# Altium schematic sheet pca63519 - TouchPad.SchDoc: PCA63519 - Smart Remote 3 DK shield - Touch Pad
size A4; DocumentNumber: 6; Revision: 1.2.1; SheetNumber: 6; SheetTotal: 6; DrawnBy: GETR; ProjectNumber: 4414; DocumentSize: A4; PCBRevision: 0049GETR; PCAName: PCA63519; PCBNumber: 400129
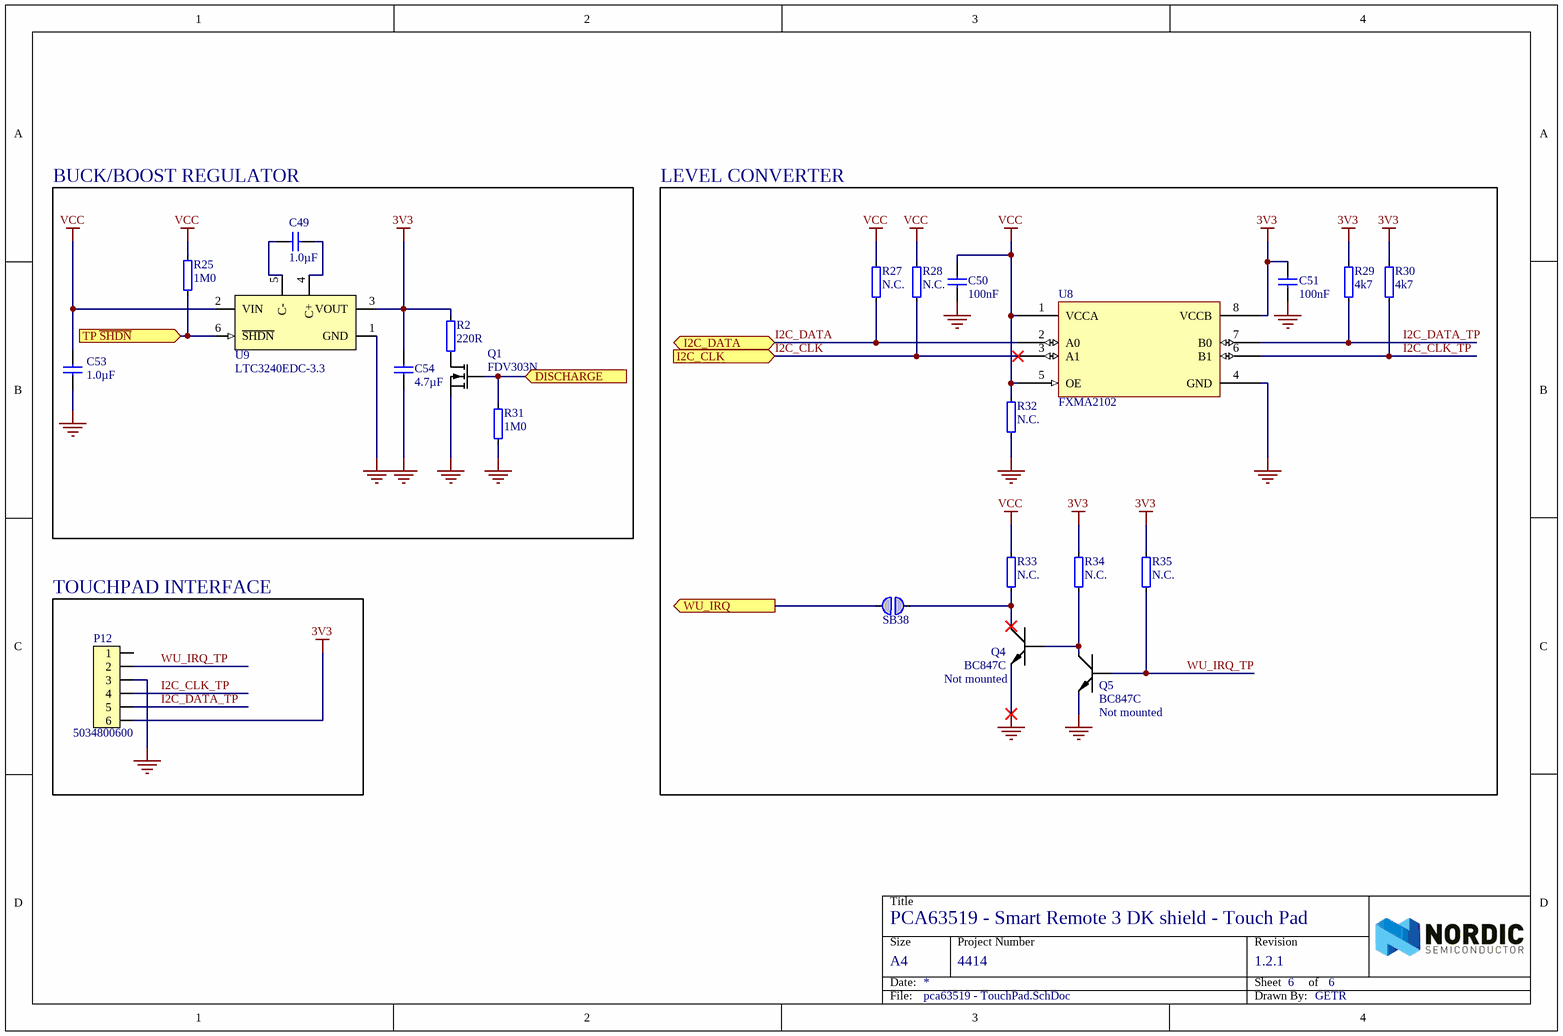
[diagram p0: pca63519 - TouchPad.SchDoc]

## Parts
C49  1.0µF  [CAPC1005X04L]
C50  100nF  [CAPC1005X04L]
C51  100nF  [CAPC1005X04L]
C53  1.0µF  [CAPC1005X04L]
C54  4.7µF  [CAPC1005X04L]
P12  5034800600  [Molex 5034800600]
Q1  FDV303N  [SOT-23a]
Q4  BC847C  Assembly: Not mounted  [SOT-23a]
Q5  BC847C  Assembly: Not mounted  [SOT-23a]
R2  220R  [RESC1005X04L]
R25  1M0  [RESC1005X04L]
R27  N.C.  [RESC1005X04L]
R28  N.C.  [RESC1005X04L]
R29  4k7  [RESC1005X04L]
R30  4k7  [RESC1005X04L]
R31  1M0  [RESC1005X04L]
R32  N.C.  [RESC1005X04L]
R33  N.C.  [RESC1005X04L]
R34  N.C.  [RESC1005X04L]
R35  N.C.  [RESC1005X04L]
SB38  Solderbridge  [Solderbridge_0.4]  (value not drawn)  (no BOM)
U8  FXMA2102  [QFN40P140X120X55-8N]
U9  LTC3240EDC-3.3  [SON50P200X80_HS-7N]

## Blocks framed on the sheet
BUCK/BOOST REGULATOR: C49 C53 C54 Q1 R2 R25 R31 U9
LEVEL CONVERTER: C50 C51 Q4 Q5 R27-R30 R32-R35 SB38 U8
TOUCHPAD INTERFACE: P12

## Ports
DISCHARGE (in), I2C_CLK (in), I2C_DATA (bidir), TP ~{SHDN} (in), WU_IRQ (out)

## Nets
3V3: C51.2 C54.2 P12.6 R2.2 R29.1 R30.1 R34.1 R35.1 U8.8(VCCB) U9.3(VOUT)
GND: C50.1 C51.1 C53.1 C54.1 P12.3 Q1.2(S) Q4.2(E) Q5.2(E) R31.1 R32.2 U8.4(GND) U9.1(GND) U9.7(GND)
VCC: C50.2 C53.2 R25.2 R27.1 R28.1 R32.1 R33.1 U8.1(VCCA) U8.5(OE) U9.2(VIN)
DISCHARGE: Q1.1(G) R31.2 ; port DISCHARGE
I2C_CLK: R28.2 U8.3(A1) ; port I2C_CLK
I2C_CLK_TP: P12.4 R30.2 U8.6(B1)
I2C_DATA: R27.2 U8.2(A0) ; port I2C_DATA
I2C_DATA_TP: P12.5 R29.2 U8.7(B0)
TP ~{SHDN}: R25.1 U9.6(~{SHDN}) ; port TP ~{SHDN}
WU_IRQ: SB38.2 ; port WU_IRQ
WU_IRQ_TP: P12.2 Q5.1(B) R35.2
NetC49_1: C49.1 U9.4(C+)
NetC49_2: C49.2 U9.5(C-)
NetQ1_3: Q1.3(D) R2.1
NetQ4_1: Q4.1(B) Q5.3(C) R34.2
NetQ4_3: Q4.3(C) R33.2 SB38.1

Not connected (* = marked no-connect by the designer): P12 1

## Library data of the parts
C49 C53 = C0402-1µ0: Capacitor, X5R, ±5%; Note: 6.3V; Artikkelnr Noca: 20039235; Artikkelnr Simpro: N.A.
C50 C51 = C0402-100n: Capacitor, X7R, ±10%; Note: 16V; Artikkelnr Noca: 20039200; Artikkelnr Simpro: N.A.
C54 = C0402-4µ7: Capacitor, X5R, ±20%; Note: 10V; Artikkelnr Noca: 20039482; Artikkelnr Simpro: N.A.
P12 = Molex 5034800600: CONN FFC FPC 6POS 0.50MM R/A; Manufacturer: Molex; Artikkelnr Noca: N.A.
Q1 = FDV303N: Mosfet FDV303N; 2nd source part number: FDV303NCT-ND; Note: Schottky; Artikkelnr Noca: 35029048; Artikkelnr Simpro: N.A.
Q4 Q5 = BC847C: BC847C, NPN Silicon transistor; Manufacturer: NXP; 2nd source part number: 568-1636-1-ND; Note: NPN Epitaxial Silicon Transistor; Artikkelnr Noca: 35019020; Artikkelnr Simpro: N.A.
R2 = R0402-220: Resistor, ±1%, 0.063W; Note: Chip Res 1%; Artikkelnr Noca: 27049057; Artikkelnr Simpro: N.A.; Value Ohm: 220
R25 R31 = R0402-1M0: Resistor, ±1%, 0.063W; Note: Chip Res 1%; Artikkelnr Noca: 27049145; Artikkelnr Simpro: N.A.; Value Ohm: 1000000
R27 R28 R32-R35 = R0402-N.C.: Not mounted; Note: Chip Res; Artikkelnr Noca: N.A.; Assembly: Not mounted
R29 R30 = R0402-4k7: Resistor, ±1%, 0.063W; Note: Chip Res 1%; Artikkelnr Noca: 27049089; Artikkelnr Simpro: N.A.; Value Ohm: 4700
SB38 = Solderbridge 0.4mm: Artikkelnr Noca: N.A.
U8 = FXMA2102: XLATOR/BUFF/REPEAT/ISOLATR 8UMLPd; Manufacturer: Fairchild; Manufacturer Part Number: FXMA2102UMX; Artikkelnr Noca: N.A.
U9 = LTC3240EDC-3.3: IC REG MULTI CONFIG 3.3V 6DFN; Manufacturer: Linear Technology; Manufacturer Part Number: LTC3240EDC-3.3#TRMPBF; Artikkelnr Noca: N.A.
